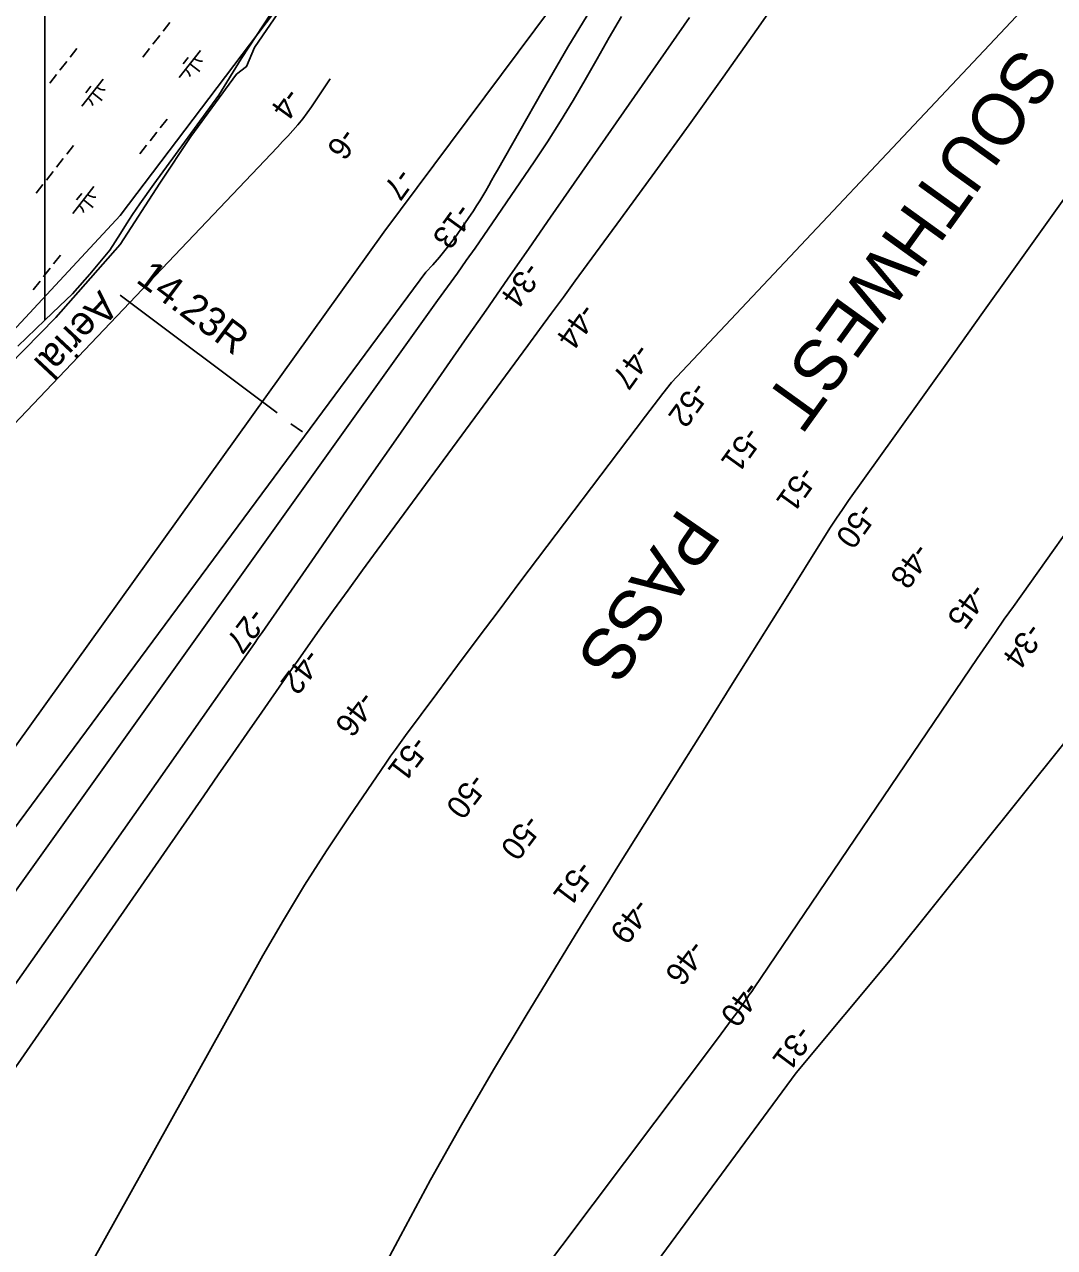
# Model space of a CAD drawing. Extents: x 3896831 to 3918110, y 171006 to 193349.
# Drawn here: x 3905950 to 3907446, y 178119 to 179895 of the extents above; entities that cross this region are included whole.
import ezdxf

# ---------------------------------------------------------------- set-up
doc = ezdxf.new("R2010")
doc.units = 0
for name, color, linetype in [('V-LEVE-TOET', 7, 'Continuous'), ('V-RIVR-EDGE', 7, 'Continuous'), ('V-RIVR-IDEN', 7, 'Continuous'), ('V-RIVR-RANG', 7, 'Continuous'), ('V-RRAP-FSHR', 7, 'Continuous'), ('V-STRM-FMON', 7, 'Continuous'), ('V-TOPO-DPTH', 7, 'Continuous'), ('V-TOPO-MAJR', 7, 'Continuous'), ('V-TOPO-MINR', 7, 'Continuous'), ('V-WETL-SWMP', 7, 'Continuous')]:
    doc.layers.add(name, color=color, linetype=linetype)

msp = doc.modelspace()

# ---------------------------------------------------------------- linework, layer by layer
at = {"layer": 'V-LEVE-TOET'}
for p, q in [((3906088.7, 179501.4), (3906316.7, 179330.6)), ((3906336.4, 179314.9), (3906353.5, 179303.1))]:
    msp.add_line(p, q, dxfattribs=at)
at = {"layer": 'V-RIVR-EDGE'}
msp.add_lwpolyline([(3906381.1, 180003.5), (3906283.5, 179861.3), (3906272.3, 179833.4), (3906257.5, 179822.3), (3906191.5, 179732.1), (3906146, 179664.3), (3906088.4, 179575.1), (3905995.4, 179469.2), (3905857, 179328.9)], dxfattribs=at)
at = {"layer": 'V-RRAP-FSHR'}
msp.add_lwpolyline([(3903099, 175512.1), (3904431.1, 177312.9), (3905197.8, 178658.5), (3906088.4, 179617.4), (3906806.7, 180565.1), (3907065.2, 181039), (3907795.1, 181990.7)], dxfattribs=at)
at = {"layer": 'V-TOPO-DPTH'}
for points in [[(3906471.6, 179592.9), (3906983, 180278.4), (3906987, 180284), (3906991, 180289.6), (3906994.9, 180295.2), (3906998.7, 180300.9), (3907032.7, 180351.5), (3907042.4, 180366.7), (3907051.6, 180382.2), (3907060, 180398), (3907068, 180414.2), (3907301.1, 181032.1), (3907308, 181046.2), (3907314.3, 181060.5), (3907319.8, 181075.1), (3907389.3, 181155), (3907466.2, 181239.5), (3907676, 181469.1), (3908331.3, 182203.1)], [(3907156.1, 180090.9), (3907013.2, 179887.4), (3906964.3, 179818.1), (3906915, 179749.1), (3906865.4, 179680.4), (3906815.4, 179611.9), (3906749.6, 179522.3), (3906732.4, 179498.8), (3906715.1, 179475.3), (3906697.8, 179451.8), (3906680.6, 179428.3), (3906461.8, 179131.3), (3906440.6, 179102.4), (3906419.6, 179073.4), (3906398.6, 179044.3), (3906377.8, 179015.1), (3906344.6, 178968.2), (3906340.5, 178962.4), (3906336.4, 178956.6), (3906332.3, 178950.8), (3906328.3, 178945), (3906294.2, 178896), (3906273.2, 178865.7), (3906252.1, 178835.4), (3906231, 178805.1), (3906210, 178774.8), (3905841, 178243.6)], [(3907156.1, 180090.9), (3907013.2, 179887.4), (3906964.3, 179818.1), (3906915, 179749.1), (3906865.4, 179680.4), (3906815.4, 179611.9), (3906749.6, 179522.3), (3906732.4, 179498.8), (3906715.1, 179475.3), (3906697.8, 179451.8), (3906680.6, 179428.3), (3906461.8, 179131.3), (3906440.6, 179102.4), (3906419.6, 179073.4), (3906398.6, 179044.3), (3906377.8, 179015.1), (3906344.6, 178968.2), (3906340.5, 178962.4), (3906336.4, 178956.6), (3906332.3, 178950.8), (3906328.3, 178945), (3906294.2, 178896), (3906273.2, 178865.7), (3906252.1, 178835.4), (3906231, 178805.1), (3906210, 178774.8), (3905841, 178243.6)], [(3906816.6, 179906.1), (3906799.1, 179875.6), (3906781.6, 179845), (3906764.2, 179814.5), (3906746.4, 179784.1), (3906728.1, 179754.1), (3906709.1, 179724.4), (3906689.7, 179695.1), (3906629.5, 179606.5), (3906616.9, 179588.1), (3906604.2, 179569.9), (3906591.4, 179551.7), (3906578.4, 179533.6), (3906549.5, 179493.7), (3905705.5, 178313.6)], [(3905705.5, 178313.6), (3906549.5, 179493.7), (3906578.4, 179533.6), (3906591.4, 179551.7), (3906604.2, 179569.9), (3906616.9, 179588.1), (3906629.5, 179606.5), (3906689.7, 179695.1), (3906709.1, 179724.4), (3906728.1, 179754.1), (3906746.4, 179784.1), (3906764.2, 179814.5), (3906781.6, 179845), (3906799.1, 179875.6), (3906816.6, 179906.1)], [(3906915.5, 179904.9), (3906713.9, 179614.7), (3906682.6, 179569.8), (3906651.4, 179524.9), (3906620.2, 179480), (3906588.9, 179435.2), (3906534.1, 179356.6), (3906492.2, 179296.6), (3906450.3, 179236.4), (3906408.6, 179176.3), (3906366.9, 179116), (3906295, 179012), (3906289.3, 179003.8), (3906283.6, 178995.6), (3906277.8, 178987.4), (3906272.1, 178979.2), (3905798.1, 178305.1)], [(3905798.1, 178305.1), (3906272.1, 178979.2), (3906277.8, 178987.4), (3906283.6, 178995.6), (3906289.3, 179003.8), (3906295, 179012), (3906366.9, 179116), (3906408.6, 179176.3), (3906450.3, 179236.4), (3906492.2, 179296.6), (3906534.1, 179356.6), (3906588.9, 179435.2), (3906620.2, 179480), (3906651.4, 179524.9), (3906682.6, 179569.8), (3906713.9, 179614.7), (3906915.5, 179904.9)], [(3905595.8, 178372), (3906471.6, 179592.9)], [(3906458.3, 177760.3), (3906956.1, 178421.9), (3906961.5, 178429.1), (3906966.9, 178436.4), (3906972.3, 178443.6), (3906977.7, 178450.8), (3906987.5, 178464), (3906988, 178464.6), (3906989.4, 178466.6), (3906995.4, 178475.4), (3906998.9, 178480.5), (3907002.4, 178485.5), (3907005.9, 178490.6), (3907009.3, 178495.7), (3907333.5, 178974.1), (3907346.5, 178993.1), (3907359.6, 179012), (3907372.7, 179030.9), (3907386, 179049.7), (3907515.6, 179231.7)], [(3906458.3, 177760.3), (3906956.1, 178421.9), (3906961.5, 178429.1), (3906966.9, 178436.4), (3906972.3, 178443.6), (3906977.7, 178450.8), (3906987.5, 178464), (3906988, 178464.6), (3906989.4, 178466.6), (3906995.4, 178475.4), (3906998.9, 178480.5), (3907002.4, 178485.5), (3907005.9, 178490.6), (3907009.3, 178495.7), (3907333.5, 178974.1), (3907346.5, 178993.1), (3907359.6, 179012), (3907372.7, 179030.9), (3907386, 179049.7), (3907515.6, 179231.7)], [(3906272.9, 176861.8), (3906300.4, 176895.2), (3906332.6, 176961.8), (3906341.8, 177070.4), (3906339.2, 177184.2), (3906362.9, 177321.4), (3906430.7, 177464), (3906537.1, 177620.2), (3906753.4, 177941.9), (3907070.6, 178372.2), (3907209.4, 178539), (3907459.1, 178850.4)], [(3907459.1, 178850.4), (3907209.4, 178539), (3907070.6, 178372.2), (3906753.4, 177941.9), (3906537.1, 177620.2), (3906430.7, 177464), (3906362.9, 177321.4), (3906339.2, 177184.2), (3906341.8, 177070.4), (3906332.6, 176961.8), (3906300.4, 176895.2), (3906272.9, 176861.8)]]:
    msp.add_lwpolyline(points, dxfattribs=at)
at = {"layer": 'V-TOPO-MAJR'}
for points in [[(3907413.7, 179932), (3906889.3, 179374.8), (3906876.7, 179358.6), (3906864.2, 179342.3), (3906851.7, 179325.9), (3906669.3, 179084.7), (3906638.9, 179044.4), (3906608.6, 179004.1), (3906578.5, 178963.7), (3906548.4, 178923.2), (3906503, 178862), (3906495.8, 178852), (3906488.6, 178842.1), (3906481.5, 178832.1), (3906474.5, 178822), (3906421.2, 178744.3), (3906388.3, 178694.9), (3906356.3, 178645), (3906325.7, 178594.1), (3906296, 178542.8), (3906026.7, 178059.9)], [(3906437.2, 178025.7), (3906495.6, 178135.8), (3906539.5, 178216.8), (3906584.3, 178297.1), (3906630.7, 178376.6), (3906678.1, 178455.6), (3906749.6, 178572.3), (3906764.9, 178597.3), (3906780.3, 178622.2), (3906795.8, 178647), (3906811.3, 178671.8), (3906902.8, 178817.6), (3906940.5, 178877.6), (3906978.2, 178937.7), (3907015.8, 178997.8), (3907053.4, 179057.8), (3907112.1, 179151.6), (3907120.5, 179164.8), (3907129, 179177.8), (3907137.8, 179190.6), (3907146.7, 179203.4), (3907213.7, 179297.3), (3907256.3, 179357), (3907298.8, 179416.6), (3907341.5, 179476.2), (3907384.1, 179535.8), (3907563.5, 179786.5)]]:
    msp.add_lwpolyline(points, dxfattribs=at)
at = {"layer": 'V-TOPO-MINR'}
for points in [[(3908331.3, 182203.1), (3907676, 181469.1), (3907466.2, 181239.5), (3907389.3, 181155), (3907319.8, 181075.1), (3907314.3, 181060.5), (3907308, 181046.2), (3907301.1, 181032.1), (3907068, 180414.2), (3907060, 180398), (3907051.6, 180382.2), (3907042.4, 180366.7), (3907032.7, 180351.5), (3906998.7, 180300.9), (3906994.9, 180295.2), (3906991, 180289.6), (3906987, 180284), (3906983, 180278.4), (3906471.6, 179592.9)], [(3907156.1, 180090.9), (3907013.2, 179887.4), (3906964.3, 179818.1), (3906915, 179749.1), (3906865.4, 179680.4), (3906815.4, 179611.9), (3906749.6, 179522.3), (3906732.4, 179498.8), (3906715.1, 179475.3), (3906697.8, 179451.8), (3906680.6, 179428.3), (3906461.8, 179131.3), (3906440.6, 179102.4), (3906419.6, 179073.4), (3906398.6, 179044.3), (3906377.8, 179015.1), (3906344.6, 178968.2), (3906340.5, 178962.4), (3906336.4, 178956.6), (3906332.3, 178950.8), (3906328.3, 178945), (3906294.2, 178896), (3906273.2, 178865.7), (3906252.1, 178835.4), (3906231, 178805.1), (3906210, 178774.8), (3905841, 178243.6)], [(3906777.5, 179925), (3906739, 179861.6), (3906701.5, 179797.5), (3906636.7, 179683.1), (3906632.5, 179675.7), (3906628.2, 179668.2), (3906624, 179660.7), (3906619.8, 179653.3), (3906615.4, 179645.8), (3906611, 179638.5), (3906606.4, 179631.3), (3906601.6, 179624.1), (3906586.5, 179601.9), (3906583.4, 179597.3), (3906580.2, 179592.8), (3906576.9, 179588.4), (3906573.6, 179584), (3906562, 179568.7), (3906552.5, 179556.9), (3906542.7, 179545.5), (3906532.4, 179534.8), (3905650.8, 178344.2)], [(3906816.6, 179906.1), (3906799.1, 179875.6), (3906781.6, 179845), (3906764.2, 179814.5), (3906746.4, 179784.1), (3906728.1, 179754.1), (3906709.1, 179724.4), (3906689.7, 179695.1), (3906629.5, 179606.5), (3906616.9, 179588.1), (3906604.2, 179569.9), (3906591.4, 179551.7), (3906578.4, 179533.6), (3906549.5, 179493.7), (3905705.5, 178313.6)], [(3906915.5, 179904.9), (3906713.9, 179614.7), (3906682.6, 179569.8), (3906651.4, 179524.9), (3906620.2, 179480), (3906588.9, 179435.2), (3906534.1, 179356.6), (3906492.2, 179296.6), (3906450.3, 179236.4), (3906408.6, 179176.3), (3906366.9, 179116), (3906295, 179012), (3906289.3, 179003.8), (3906283.6, 178995.6), (3906277.8, 178987.4), (3906272.1, 178979.2), (3905798.1, 178305.1)], [(3906393.4, 179815.8), (3906366.6, 179775.3), (3906360.4, 179766.3), (3906353.8, 179757.5), (3906346.9, 179749), (3906339.6, 179740.8), (3906332.1, 179732.7), (3906324.6, 179724.7), (3906317.1, 179716.7), (3905327.1, 178676.1)], [(3906471.6, 179592.9), (3905595.8, 178372)], [(3906458.3, 177760.3), (3906956.1, 178421.9), (3906961.5, 178429.1), (3906966.9, 178436.4), (3906972.3, 178443.6), (3906977.7, 178450.8), (3906987.5, 178464), (3906988, 178464.6), (3906989.4, 178466.6), (3906995.4, 178475.4), (3906998.9, 178480.5), (3907002.4, 178485.5), (3907005.9, 178490.6), (3907009.3, 178495.7), (3907333.5, 178974.1), (3907346.5, 178993.1), (3907359.6, 179012), (3907372.7, 179030.9), (3907386, 179049.7), (3907515.6, 179231.7)], [(3907459.1, 178850.4), (3907209.4, 178539), (3907070.6, 178372.2), (3906753.4, 177941.9), (3906537.1, 177620.2), (3906430.7, 177464), (3906362.9, 177321.4), (3906339.2, 177184.2), (3906341.8, 177070.4), (3906332.6, 176961.8), (3906300.4, 176895.2), (3906272.9, 176861.8)]]:
    msp.add_lwpolyline(points, dxfattribs=at)
at = {"layer": 'V-WETL-SWMP'}
for p, q in [((3905979.3, 184854.9), (3905979.3, 179465.2)), ((3905979.3, 179465.2), (3905979.3, 184854.9)), ((3906264.2, 179844.6), (3906307.9, 179910.9)), ((3906160.9, 179897.6), (3906151, 179885)), ((3906146.1, 179878.7), (3906136.2, 179866.1)), ((3906025.8, 179860), (3906015.9, 179847.4)), ((3906131.2, 179859.8), (3906121.4, 179847.2)), ((3906205.4, 179857.1), (3906174.5, 179817.7)), ((3906011, 179841.1), (3906001.1, 179828.5)), ((3906187.6, 179846.9), (3906180.2, 179837.5)), ((3906190, 179837.4), (3906204.1, 179826.3)), ((3906231.7, 179792), (3906264.2, 179844.6)), ((3905996.2, 179822.2), (3905986.3, 179809.6)), ((3906064, 179815.2), (3906033.1, 179775.8)), ((3906046.2, 179805), (3906038.8, 179795.5)), ((3906048.6, 179795.5), (3906062.7, 179784.4)), ((3906137.4, 179662.6), (3906231.7, 179792)), ((3906156.7, 179757.4), (3906146.8, 179744.8)), ((3906141.9, 179738.5), (3906132, 179725.9)), ((3906020.9, 179719), (3906011, 179706.4)), ((3906127.1, 179719.6), (3906117.2, 179707)), ((3906006, 179700.1), (3905996.2, 179687.5)), ((3905991.2, 179681.2), (3905981.4, 179668.6)), ((3905976.4, 179662.3), (3905966.6, 179649.7)), ((3906050.6, 179659.6), (3906019.7, 179620.2)), ((3906117.3, 179634.2), (3906137.4, 179662.6)), ((3906032.8, 179649.4), (3906025.4, 179639.9)), ((3906035.2, 179639.9), (3906049.3, 179628.8)), ((3906106.7, 179618.5), (3906117.3, 179634.2)), ((3906088.9, 179590.9), (3906098, 179605.3)), ((3906098, 179605.3), (3906106.7, 179618.5)), ((3906073.7, 179566.9), (3906088.9, 179590.9)), ((3906001.9, 179559.8), (3905992, 179547.2)), ((3906044.4, 179532.1), (3906073.7, 179566.9)), ((3905987.1, 179540.9), (3905979.3, 179531.1)), ((3905972.3, 179522.1), (3905962.4, 179509.5)), ((3905979.3, 179531.1), (3905977.2, 179528.4)), ((3906019.2, 179503.7), (3906044.4, 179532.1)), ((3906000.6, 179485.6), (3906019.2, 179503.7)), ((3905979.3, 179465.2), (3906000.6, 179485.6)), ((3905940.2, 179427.7), (3905979.3, 179465.2))]:
    msp.add_line(p, q, dxfattribs=at)
for centre, start, end in [((3906207.2, 179859), 231.1403, 272.6839), ((3906173.1, 179815.5), 11.1403, 52.6839), ((3906065.8, 179817.1), 231.1403, 272.6839), ((3906031.7, 179773.6), 11.1403, 52.6839), ((3906052.4, 179661.5), 231.1403, 272.6839), ((3906018.3, 179618), 11.1403, 52.6839)]:
    msp.add_arc(centre, 17.6, start, end, dxfattribs=at)

# ---------------------------------------------------------------- texts
at = {"layer": 'V-RIVR-IDEN'}
for s, height, rotation, p in [('SOUTHWEST', 75, 234.2369, (3907395.4, 179865.2)), ('Aerial', 42, 226.8483, (3906059, 179510)), ('PASS', 75, 235.3849, (3906901.7, 179195))]:
    msp.add_text(s, height=height, rotation=rotation, dxfattribs=at).set_placement(p)
at = {"layer": 'V-RIVR-RANG'}
for s, rotation, p in [('-4', 234.1483, (3906329.5, 179805.2)), ('-6', 234.1483, (3906410.8, 179746.9)), ('-7', 234.1483, (3906492, 179688.5)), ('-13', 234.1483, (3906578.6, 179637.6)), ('-34', 234.2903, (3906678, 179552.3)), ('-44', 234.2903, (3906758.5, 179492.2)), ('-47', 234.2903, (3906838.1, 179433.8)), ('-52', 234.2903, (3906920.8, 179378.6)), ('-51', 234.2903, (3906997.5, 179313.2)), ('-51', 234.2903, (3907077.7, 179255.6)), ('-50', 234.2903, (3907164, 179202.6)), ('-48', 234.2903, (3907243.2, 179144.2)), ('-45', 234.2903, (3907325.8, 179085.5)), ('-27', 232.9921, (3906278.6, 179050.1)), ('-34', 234.2903, (3907407, 179028.3)), ('-42', 232.9921, (3906358.8, 178990.6)), ('-46', 232.9921, (3906438, 178929.2)), ('-51', 232.9921, (3906514.6, 178864.1)), ('-50', 232.9921, (3906598.9, 178809.8)), ('-50', 232.9921, (3906678.2, 178750)), ('-51', 232.9921, (3906754.7, 178683.1)), ('-49', 232.9921, (3906837.1, 178628.3)), ('-46', 232.9921, (3906917.4, 178567.9)), ('-40', 232.9921, (3906997.6, 178507.9)), ('-31', 232.9921, (3907073.2, 178444))]:
    msp.add_text(s, height=33.5, rotation=rotation, dxfattribs=at).set_placement(p)
at = {"layer": 'V-STRM-FMON'}
msp.add_text('14.23R', height=42, rotation=323.1574, dxfattribs=at).set_placement((3906110, 179521.6))

doc.saveas('drawing.dxf')
